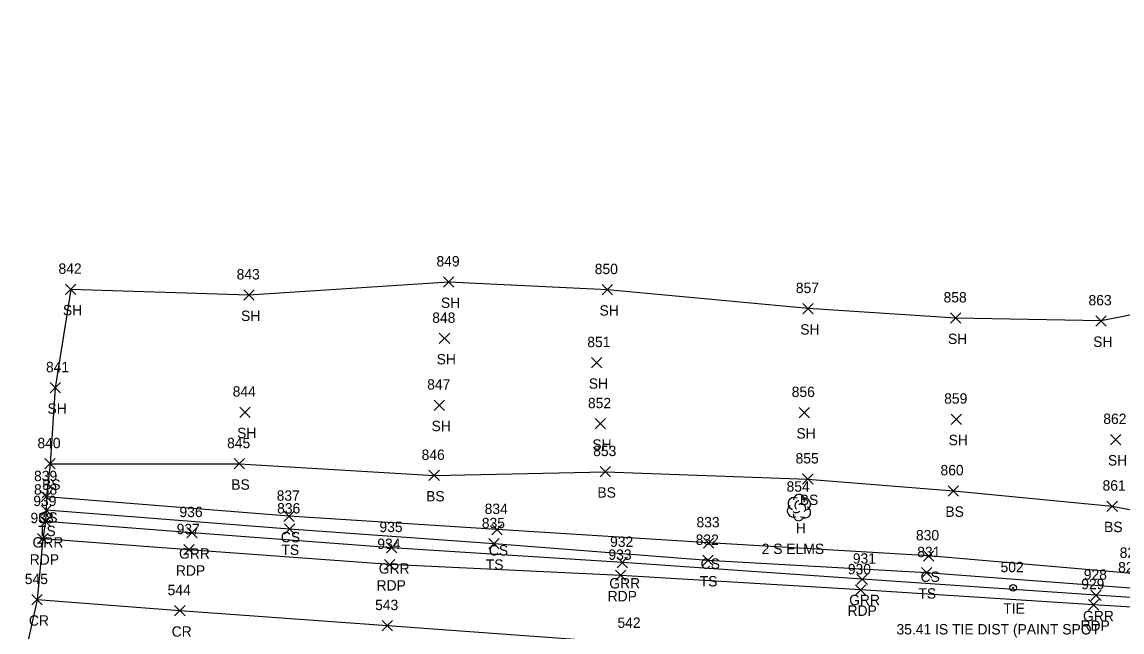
# Model space of a CAD drawing. Extents: x 1679360 to 1685861, y 903420 to 905946.
# Drawn here: x 1679464.4 to 1679676.5, y 904048.5 to 904166 of the extents above; entities that cross this region are included whole.
import ezdxf

# ---------------------------------------------------------------- set-up
doc = ezdxf.new("R2010")
doc.units = 0
for name, color, linetype in [('C_A', 7, 'Continuous'), ('C_C', 7, 'Continuous'), ('C_I', 7, 'Continuous'), ('CBP', 7, 'Continuous'), ('L_A', 7, 'Continuous'), ('L_C', 7, 'Continuous'), ('L_I', 7, 'Continuous'), ('L_TIC', 7, 'Continuous'), ('LELB', 7, 'Continuous'), ('LSOGP', 7, 'Continuous'), ('LTD', 7, 'Continuous'), ('P_A', 7, 'Continuous'), ('P_I', 7, 'Continuous'), ('P_TIC', 7, 'Continuous'), ('PET', 7, 'Continuous'), ('PRC', 7, 'Continuous'), ('R_A', 7, 'Continuous'), ('R_I', 7, 'Continuous'), ('R_TIC', 7, 'Continuous'), ('RGR', 7, 'Continuous')]:
    doc.layers.add(name, color=color, linetype=linetype)

msp = doc.modelspace()

# ---------------------------------------------------------------- linework, layer by layer
at = {"layer": 'CBP'}
for radius in [0.625, 0.0833]:
    msp.add_circle((1679655.52, 904056.98), radius, dxfattribs=at)
at = {"layer": 'L_TIC'}
for points in [[(1679472.84, 904113.46), (1679474.84, 904115.46)], [(1679474.84, 904113.46), (1679472.84, 904115.46)], [(1679545.71, 904114.88), (1679547.71, 904116.88)], [(1679547.71, 904114.88), (1679545.71, 904116.88)], [(1679576.3, 904113.4), (1679578.3, 904115.4)], [(1679578.3, 904113.4), (1679576.3, 904115.4)], [(1679507.18, 904112.37), (1679509.18, 904114.37)], [(1679509.18, 904112.37), (1679507.18, 904114.37)], [(1679614.98, 904109.75), (1679616.98, 904111.75)], [(1679616.98, 904109.75), (1679614.98, 904111.75)], [(1679643.45, 904107.94), (1679645.45, 904109.94)], [(1679645.45, 904107.94), (1679643.45, 904109.94)], [(1679671.44, 904107.38), (1679673.44, 904109.38)], [(1679673.44, 904107.38), (1679671.44, 904109.38)], [(1679544.89, 904104.01), (1679546.89, 904106.01)], [(1679546.89, 904104.01), (1679544.89, 904106.01)], [(1679574.21, 904099.33), (1679576.21, 904101.33)], [(1679576.21, 904099.33), (1679574.21, 904101.33)], [(1679469.87, 904094.5), (1679471.87, 904096.5)], [(1679471.87, 904094.5), (1679469.87, 904096.5)], [(1679506.42, 904089.8), (1679508.42, 904091.8)], [(1679508.42, 904089.8), (1679506.42, 904091.8)], [(1679543.91, 904091.14), (1679545.91, 904093.14)], [(1679545.91, 904091.14), (1679543.91, 904093.14)], [(1679614.24, 904089.72), (1679616.24, 904091.72)], [(1679616.24, 904089.72), (1679614.24, 904091.72)], [(1679574.91, 904087.57), (1679576.91, 904089.57)], [(1679576.91, 904087.57), (1679574.91, 904089.57)], [(1679643.58, 904088.44), (1679645.58, 904090.44)], [(1679645.58, 904088.44), (1679643.58, 904090.44)], [(1679674.29, 904084.53), (1679676.29, 904086.53)], [(1679676.29, 904084.53), (1679674.29, 904086.53)], [(1679468.87, 904079.86), (1679470.87, 904081.86)], [(1679470.87, 904079.86), (1679468.87, 904081.86)], [(1679505.34, 904079.86), (1679507.34, 904081.86)], [(1679507.34, 904079.86), (1679505.34, 904081.86)], [(1679542.9, 904077.61), (1679544.9, 904079.61)], [(1679544.9, 904077.61), (1679542.9, 904079.61)], [(1679575.91, 904078.34), (1679577.91, 904080.34)], [(1679577.91, 904078.34), (1679575.91, 904080.34)], [(1679614.93, 904076.92), (1679616.93, 904078.92)], [(1679616.93, 904076.92), (1679614.93, 904078.92)], [(1679468.14, 904073.52), (1679470.14, 904075.52)], [(1679470.14, 904073.52), (1679468.14, 904075.52)], [(1679643, 904074.64), (1679645, 904076.64)], [(1679645, 904074.64), (1679643, 904076.64)], [(1679468.12, 904070.92), (1679470.12, 904072.92)], [(1679470.12, 904070.92), (1679468.12, 904072.92)], [(1679673.59, 904071.69), (1679675.59, 904073.69)], [(1679675.59, 904071.69), (1679673.59, 904073.69)], [(1679514.9, 904069.74), (1679516.9, 904071.74)], [(1679516.9, 904069.74), (1679514.9, 904071.74)], [(1679515.04, 904067.29), (1679517.04, 904069.29)], [(1679517.04, 904067.29), (1679515.04, 904069.29)], [(1679555, 904067.19), (1679557, 904069.19)], [(1679557, 904067.19), (1679555, 904069.19)], [(1679554.45, 904064.45), (1679556.45, 904066.45)], [(1679556.45, 904064.45), (1679554.45, 904066.45)], [(1679595.82, 904064.62), (1679597.82, 904066.62)], [(1679597.82, 904064.62), (1679595.82, 904066.62)], [(1679638.22, 904062.11), (1679640.22, 904064.11)], [(1679640.22, 904062.11), (1679638.22, 904064.11)], [(1679595.67, 904061.24), (1679597.67, 904063.24)], [(1679597.67, 904061.24), (1679595.67, 904063.24)], [(1679637.82, 904058.88), (1679639.82, 904060.88)], [(1679639.82, 904058.88), (1679637.82, 904060.88)]]:
    msp.add_lwpolyline(points, dxfattribs=at)
at = {"layer": 'LELB'}
for points in [[(1679619.82, 904321.42), (1679641.86, 904284.96), (1679662.72, 904251.2), (1679682.47, 904216.95), (1679699.46, 904186.97), (1679725.72, 904150), (1679749.74, 904116.77), (1679771.88, 904083.62), (1679794.81, 904052.66), (1679781.37, 904055.05), (1679771.63, 904053.63), (1679751.57, 904052.46), (1679718.64, 904054.59), (1679678.1, 904056.93), (1679638.82, 904059.88), (1679596.67, 904062.24), (1679555.45, 904065.45), (1679516.04, 904068.29), (1679469.12, 904071.92)], [(1679613.72, 904318.48), (1679636.27, 904281.99), (1679658.68, 904248.53), (1679679.07, 904215.01), (1679696.37, 904185.6), (1679721.82, 904147.6), (1679745.3, 904114.19), (1679768.75, 904081.07), (1679780.23, 904064.6), (1679777.26, 904058.93), (1679769.31, 904058.16), (1679752.16, 904056.65), (1679719.29, 904057.03), (1679678.41, 904059.75), (1679639.22, 904063.11), (1679596.82, 904065.62), (1679556, 904068.19), (1679515.9, 904070.74), (1679469.14, 904074.52)], [(1679469.87, 904080.86), (1679506.34, 904080.86), (1679543.9, 904078.61), (1679576.91, 904079.34), (1679615.93, 904077.92), (1679644, 904075.64), (1679674.59, 904072.69), (1679700.8, 904067.68), (1679715.25, 904064.96), (1679721.21, 904064.56), (1679726.22, 904064.25), (1679732.36, 904064.22), (1679738.12, 904066.05), (1679742.62, 904068.56), (1679755.32, 904068.1), (1679769.59, 904069.28), (1679758.63, 904082.85), (1679744.91, 904103.49), (1679726.51, 904128.69), (1679708.52, 904157.77), (1679684.84, 904191.6)]]:
    msp.add_lwpolyline(points, dxfattribs=at)
at = {"layer": 'LSOGP'}
msp.add_lwpolyline([(1679693.3, 904112.54), (1679672.44, 904108.38), (1679644.45, 904108.94), (1679615.98, 904110.75), (1679577.3, 904114.4), (1679546.71, 904115.88), (1679508.18, 904113.37), (1679473.84, 904114.46), (1679470.87, 904095.5), (1679469.87, 904080.86), (1679469.14, 904074.52), (1679469.12, 904071.92), (1679469, 904069.72), (1679468.44, 904066.43), (1679467.34, 904054.68), (1679464.45, 904041.77)], dxfattribs=at)
at = {"layer": 'LTD'}
msp.add_line((1679614.19, 904072.48), (1679614.19, 904072.48), dxfattribs=at)
msp.add_line((1679614.19, 904072.48), (1679614.19, 904072.48), dxfattribs=at)
msp.add_arc((1679614.24, 904073.91), 1.05, 335.5272, 180.9563, dxfattribs=at)
for centre, major_axis, ratio, start_param, end_param in [((1679613.11, 904071.77), (0.58, -1.04), 0.959034, 3.141593, 6.283185), ((1679613.4, 904073.15), (1.21, -0.51), 0.895232, 1.570796, 4.712389), ((1679613.98, 904072.94), (-0.208, -0.792), 0.645439, 3.141593, 6.283185), ((1679614.69, 904072.31), (-0.5, 0.667), 0.989748, 3.141593, 6.283185), ((1679615.19, 904071.65), (-1.09, 0.79), 0.841452, 1.570796, 4.712389), ((1679615.23, 904073.06), (-1.14, -0.48), 0.949671, 1.570796, 4.712389), ((1679614.19, 904070.98), (0.26, 1.06), 0.942809, 1.570796, 4.712389), ((1679613.73, 904071.73), (-0.625, -0.083), 0.423636, 0, 3.141593)]:
    msp.add_ellipse(centre, major_axis=major_axis, ratio=ratio, start_param=start_param, end_param=end_param, dxfattribs=at)
at = {"layer": 'P_TIC'}
for points in [[(1679467.44, 904065.43), (1679469.44, 904067.43)], [(1679469.44, 904065.43), (1679467.44, 904067.43)], [(1679495.62, 904063.3), (1679497.62, 904065.3)], [(1679497.62, 904063.3), (1679495.62, 904065.3)], [(1679534.31, 904060.44), (1679536.31, 904062.44)], [(1679536.31, 904060.44), (1679534.31, 904062.44)], [(1679578.85, 904058.36), (1679580.85, 904060.36)], [(1679580.85, 904058.36), (1679578.85, 904060.36)], [(1679466.34, 904053.68), (1679468.34, 904055.68)], [(1679468.34, 904053.68), (1679466.34, 904055.68)], [(1679625.09, 904055.57), (1679627.09, 904057.57)], [(1679627.09, 904055.57), (1679625.09, 904057.57)], [(1679493.87, 904051.55), (1679495.87, 904053.55)], [(1679495.87, 904051.55), (1679493.87, 904053.55)], [(1679670, 904052.69), (1679672, 904054.69)], [(1679672, 904052.69), (1679670, 904054.69)], [(1679533.87, 904048.67), (1679535.87, 904050.67)], [(1679535.87, 904048.67), (1679533.87, 904050.67)]]:
    msp.add_lwpolyline(points, dxfattribs=at)
at = {"layer": 'PET'}
msp.add_lwpolyline([(1680210.84, 904017.73), (1680154.55, 904022.58), (1680102.27, 904026.43), (1680051.74, 904029.42), (1680001.13, 904032.43), (1679941.04, 904036.26), (1679894.06, 904039.28), (1679848.46, 904042.23), (1679824.08, 904043.91), (1679814.8, 904045.29), (1679808.83, 904044.91), (1679764.15, 904047.76), (1679716.13, 904050.9), (1679671, 904053.69), (1679626.09, 904056.57), (1679579.85, 904059.36), (1679535.31, 904061.44), (1679496.62, 904064.3), (1679468.44, 904066.43)], dxfattribs=at)
at = {"layer": 'PRC'}
msp.add_lwpolyline([(1680209.65, 904002.04), (1680152.97, 904005.78), (1680100.29, 904009.57), (1680049.21, 904012.91), (1679999.46, 904016.39), (1679940.5, 904020.99), (1679893.64, 904024.04), (1679847.03, 904027.44), (1679827.53, 904028.69), (1679808.61, 904029.86), (1679757.07, 904033.5), (1679707.39, 904036.98), (1679666.22, 904040.39), (1679623.03, 904043.25), (1679581.59, 904046.25), (1679534.87, 904049.67), (1679494.87, 904052.55), (1679467.34, 904054.68)], dxfattribs=at)
at = {"layer": 'R_TIC'}
for points in [[(1679468, 904068.72), (1679470, 904070.72)], [(1679470, 904068.72), (1679468, 904070.72)], [(1679496.22, 904066.59), (1679498.22, 904068.59)], [(1679498.22, 904066.59), (1679496.22, 904068.59)], [(1679534.72, 904063.7), (1679536.72, 904065.7)], [(1679536.72, 904063.7), (1679534.72, 904065.7)], [(1679579.17, 904060.85), (1679581.17, 904062.85)], [(1679581.17, 904060.85), (1679579.17, 904062.85)], [(1679625.4, 904057.62), (1679627.4, 904059.62)], [(1679627.4, 904057.62), (1679625.4, 904059.62)], [(1679670.48, 904054.53), (1679672.48, 904056.53)], [(1679672.48, 904054.53), (1679670.48, 904056.53)]]:
    msp.add_lwpolyline(points, dxfattribs=at)
at = {"layer": 'RGR'}
msp.add_lwpolyline([(1679781.27, 904053.66), (1679773.63, 904050.71), (1679763.81, 904049.54), (1679716.12, 904052.56), (1679671.48, 904055.53), (1679626.4, 904058.62), (1679580.17, 904061.85), (1679535.72, 904064.7), (1679497.22, 904067.59), (1679469, 904069.72)], dxfattribs=at)

# ---------------------------------------------------------------- texts
at = {"layer": 'C_A'}
msp.add_text('TIE', height=2, dxfattribs=at).set_placement((1679653.6, 904051.98))
at = {"layer": 'C_C'}
msp.add_text('35.41 IS TIE DIST (PAINT SPOT', height=2, dxfattribs=at).set_placement((1679633.02, 904047.98))
at = {"layer": 'C_I'}
msp.add_text('502', height=2, dxfattribs=at).set_placement((1679653.08, 904059.98))
at = {"layer": 'L_A'}
for s, p in [('SH', (1679545.2, 904110.88)), ('SH', (1679472.33, 904109.46)), ('SH', (1679575.78, 904109.4)), ('SH', (1679506.67, 904108.37)), ('SH', (1679614.47, 904105.75)), ('SH', (1679642.94, 904103.94)), ('SH', (1679670.93, 904103.38)), ('SH', (1679544.38, 904100.01)), ('SH', (1679573.7, 904095.33)), ('SH', (1679469.35, 904090.5)), ('SH', (1679505.91, 904085.8)), ('SH', (1679543.4, 904087.14)), ('SH', (1679613.73, 904085.72)), ('SH', (1679574.39, 904083.57)), ('SH', (1679643.07, 904084.44)), ('SH', (1679673.77, 904080.53)), ('BS', (1679468.31, 904075.86)), ('BS', (1679504.78, 904075.86)), ('BS', (1679542.34, 904073.61)), ('BS', (1679575.36, 904074.34)), ('BS', (1679614.37, 904072.92)), ('BS', (1679642.44, 904070.64)), ('CS', (1679467.58, 904069.52)), ('TS', (1679467.53, 904066.92)), ('H', (1679613.62, 904067.48)), ('BS', (1679673.03, 904067.69)), ('CS', (1679514.34, 904065.74)), ('TS', (1679514.45, 904063.29)), ('CS', (1679554.44, 904063.19)), ('TS', (1679553.85, 904060.45)), ('CS', (1679595.26, 904060.62)), ('CS', (1679637.66, 904058.11)), ('TS', (1679595.08, 904057.24)), ('TS', (1679637.23, 904054.88))]:
    msp.add_text(s, height=2, dxfattribs=at).set_placement(p)
at = {"layer": 'L_C'}
msp.add_text('2 S ELMS', height=2, dxfattribs=at).set_placement((1679607.03, 904063.48))
at = {"layer": 'L_I'}
for s, p in [('842', (1679471.48, 904117.46)), ('849', (1679544.34, 904118.88)), ('850', (1679574.85, 904117.4)), ('843', (1679505.82, 904116.37)), ('857', (1679613.62, 904113.75)), ('858', (1679642.09, 904111.94)), ('863', (1679670.03, 904111.38)), ('848', (1679543.53, 904108.01)), ('851', (1679573.41, 904103.33)), ('841', (1679469.07, 904098.5)), ('847', (1679542.55, 904095.14)), ('844', (1679505.06, 904093.8)), ('856', (1679612.82, 904093.72)), ('859', (1679642.21, 904092.44)), ('852', (1679573.54, 904091.57)), ('862', (1679672.88, 904088.53)), ('840', (1679467.42, 904083.86)), ('845', (1679503.98, 904083.86)), ('846', (1679541.48, 904081.61)), ('853', (1679574.55, 904082.34)), ('855', (1679613.56, 904080.92)), ('839', (1679466.77, 904077.52)), ('860', (1679641.5, 904078.64)), ('838', (1679466.76, 904074.92)), ('854', (1679611.83, 904075.48)), ('861', (1679672.74, 904075.69)), ('837', (1679513.54, 904073.74)), ('836', (1679513.62, 904071.29)), ('834', (1679553.63, 904071.19)), ('835', (1679553.08, 904068.45)), ('833', (1679594.46, 904068.62)), ('832', (1679594.31, 904065.24)), ('830', (1679636.77, 904066.11)), ('831', (1679637.02, 904062.88)), ('829', (1679676.04, 904062.75)), ('828', (1679675.74, 904059.93))]:
    msp.add_text(s, height=2, dxfattribs=at).set_placement(p)
at = {"layer": 'P_A'}
for s, p in [('RDP', (1679465.93, 904061.43)), ('RDP', (1679494.11, 904059.3)), ('RDP', (1679532.79, 904056.44)), ('RDP', (1679577.34, 904054.36)), ('RDP', (1679623.58, 904051.57)), ('CR', (1679465.78, 904049.68)), ('CR', (1679493.3, 904047.55)), ('RDP', (1679668.49, 904048.69))]:
    msp.add_text(s, height=2, dxfattribs=at).set_placement(p)
at = {"layer": 'P_I'}
for s, p in [('938', (1679466.08, 904069.43)), ('937', (1679494.26, 904067.3)), ('934', (1679532.94, 904064.44)), ('933', (1679577.49, 904062.36)), ('930', (1679623.64, 904059.57)), ('545', (1679464.98, 904057.68)), ('929', (1679668.63, 904056.69)), ('544', (1679492.51, 904055.55)), ('543', (1679532.51, 904052.67)), ('542', (1679579.23, 904049.25))]:
    msp.add_text(s, height=2, dxfattribs=at).set_placement(p)
at = {"layer": 'R_A'}
for p in [(1679466.48, 904064.72), (1679494.71, 904062.59), (1679533.21, 904059.7), (1679577.66, 904056.85), (1679623.89, 904053.62), (1679668.97, 904050.53)]:
    msp.add_text('GRR', height=2, dxfattribs=at).set_placement(p)
at = {"layer": 'R_I'}
for s, p in [('939', (1679466.63, 904072.72)), ('936', (1679494.8, 904070.59)), ('935', (1679533.35, 904067.7)), ('932', (1679577.81, 904064.85)), ('931', (1679624.6, 904061.62)), ('928', (1679669.12, 904058.53))]:
    msp.add_text(s, height=2, dxfattribs=at).set_placement(p)

doc.saveas('drawing.dxf')
